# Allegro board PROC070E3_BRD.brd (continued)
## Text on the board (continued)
User.37: 3 - Board assembly must comply with workmanship standards IPC-A-610 Class 2, unless otherwise specified. | 4 - These assemblies are ESD sensitive, ESD precautions shall be observed. | 1 - All MSL components should be baked as per JEDEC standard. | 2 - PCB should be baked at 120 degree for 8 hours. | 6 - Provide serial numbers to the assembled boards for identification. | 7 - The assembled board are wrapped in ESD Covers(individual) and packed securely before shipment. | ASSEMBLY NOTES:- | 5 - These assemblies must be clean and free from flux and all contaminants. Use of no clean flux is not acceptable. | PROC070 E3 ASSEMBLY TOP
User.38: ASSEMBLY NOTES:- | 5 - These assemblies must be clean and free from flux and all contaminants. Use of no clean flux is not acceptable. | 1 - All MSL components should be baked as per JEDEC standard. | 2 - PCB should be baked at 120 degree for 8 hours. | 6 - Provide serial numbers to the assembled boards for identification. | 7 - The assembled board are wrapped in ESD Covers(individual) and packed securely before shipment. | 3 - Board assembly must comply with workmanship standards IPC-A-610 Class 2, unless otherwise specified. | 4 - These assemblies are ESD sensitive, ESD precautions shall be observed. | PROC070 E3 ASSEMBLY BOTTOM
